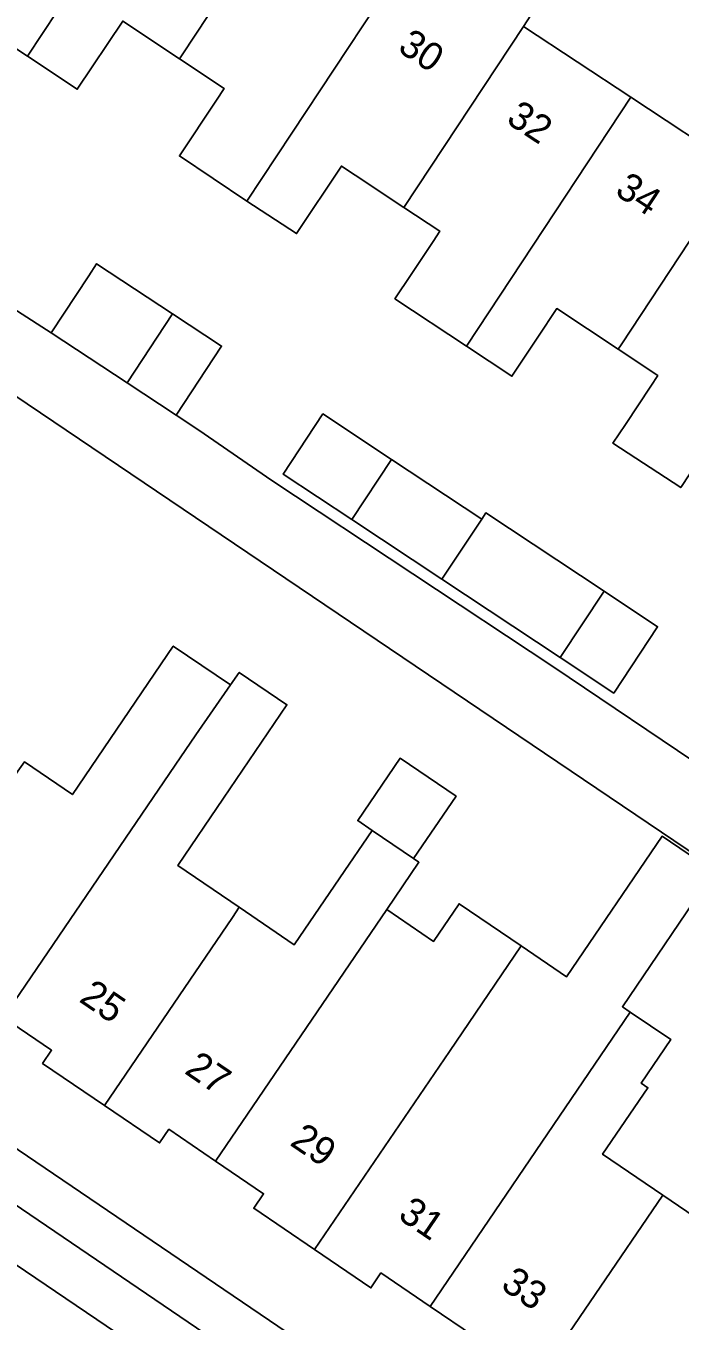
# Model space of a CAD drawing. Extents: x 159279 to 160377, y 384531 to 385888.
# Drawn here: x 159905.8 to 159929.07, y 384790.68 to 384836.73 of the extents above; entities that cross this region are included whole.
import ezdxf

# ---------------------------------------------------------------- set-up
doc = ezdxf.new("R2010")
doc.units = 0
for name, color, linetype in [('IMGEO_Erf', 7, 'Continuous'), ('IMGEO_Pand', 7, 'Continuous'), ('IMGEO_Pand_nummerreeks', 7, 'Continuous'), ('IMGEO_Parkeervlak_open', 7, 'Continuous'), ('IMGEO_Rijbaan_lokaal_open', 7, 'Continuous'), ('IMGEO_Voetpad_open', 7, 'Continuous')]:
    doc.layers.add(name, color=color, linetype=linetype)

msp = doc.modelspace()

# ---------------------------------------------------------------- linework, layer by layer
at = {"layer": 'IMGEO_Erf'}
for points in [[(159888.241, 384837.963), (159893.651, 384834.187), (159895.036, 384836.353), (159897.421, 384834.828), (159896.036, 384832.662), (159906.697, 384825.818), (159908.032, 384827.844), (159908.315, 384828.273), (159911.014, 384826.492), (159912.758, 384825.342), (159911.14, 384822.889), (159911.948, 384822.357), (159914.544, 384820.567), (159924.57, 384813.932), (159946.537, 384799.134)], [(159929.088, 384820.31), (159926.679, 384821.889), (159927.119, 384822.553), (159928.021, 384823.915), (159928.273, 384824.295), (159926.861, 384825.23), (159924.679, 384826.676), (159924.631, 384826.604), (159924.053, 384825.73), (159923.086, 384824.269), (159921.465, 384825.342), (159918.925, 384827.025), (159919.5, 384827.893), (159920.278, 384829.068), (159920.518, 384829.431), (159919.246, 384830.273), (159917.508, 384831.424), (159917.021, 384831.747), (159915.429, 384829.343), (159913.658, 384830.497), (159911.258, 384832.104), (159912.575, 384834.093), (159912.85, 384834.509), (159911.263, 384835.56), (159909.243, 384836.898), (159907.624, 384834.475), (159905.851, 384835.649), (159903.573, 384837.162)], [(159857.677, 384829.243), (159933.27, 384777.928)], [(159936.223, 384802.782), (159904.008, 384824.524)], [(159905.747, 384810.557), (159907.451, 384809.398), (159911.041, 384814.68), (159913.079, 384813.295), (159913.39, 384813.742), (159915.083, 384812.59), (159912.827, 384809.272), (159911.199, 384806.878), (159913.39, 384805.388), (159915.344, 384804.06), (159916.963, 384806.441), (159918.11, 384808.125), (159917.602, 384808.471), (159919.11, 384810.688), (159921.097, 384809.337), (159919.589, 384807.119), (159919.778, 384806.991), (159918.632, 384805.306), (159920.296, 384804.175), (159921.207, 384805.515), (159923.414, 384804.015), (159925.029, 384802.918), (159928.425, 384807.915), (159930.276, 384806.657), (159927.013, 384801.855), (159927.295, 384801.663), (159928.737, 384800.683), (159927.683, 384799.132), (159927.919, 384798.972), (159926.311, 384796.606), (159928.451, 384795.152), (159930.42, 384793.813)], [(159921.75, 384790.128), (159920.174, 384791.199), (159918.428, 384792.386), (159918.068, 384791.856), (159916.066, 384793.217), (159913.902, 384794.687), (159914.254, 384795.204), (159912.547, 384796.365), (159910.883, 384797.496), (159910.552, 384797.009), (159908.595, 384798.339), (159906.391, 384799.836), (159906.712, 384800.308), (159905.008, 384801.466)]]:
    msp.add_lwpolyline(points, dxfattribs=at)
msp.add_lwpolyline([(159922.011, 384819.189), (159922.157, 384819.41), (159926.36, 384816.626), (159928.267, 384815.362), (159926.706, 384813.005), (159924.795, 384814.271), (159920.595, 384817.052), (159917.387, 384819.177), (159914.945, 384820.795), (159916.36, 384822.932), (159918.799, 384821.316)], close=True, dxfattribs=at)
at = {"layer": 'IMGEO_Pand'}
for points in [[(159911.707, 384844.521), (159907.899, 384847.043), (159903.648, 384840.603), (159905.182, 384839.592), (159904.899, 384839.167), (159903.573, 384837.162), (159905.851, 384835.649), (159907.459, 384838.085)], [(159915.513, 384842.001), (159911.707, 384844.521), (159907.459, 384838.085), (159905.851, 384835.649), (159907.624, 384834.475), (159909.243, 384836.898), (159911.263, 384835.56), (159911.357, 384835.7)], [(159919.769, 384839.756), (159916.595, 384841.858), (159915.777, 384842.399), (159915.513, 384842.001), (159911.357, 384835.7), (159911.263, 384835.56), (159912.85, 384834.509), (159912.575, 384834.093), (159911.258, 384832.104), (159913.658, 384830.497), (159915.255, 384832.916)], [(159923.497, 384836.712), (159923.762, 384837.112), (159922.937, 384837.658), (159919.769, 384839.756), (159915.255, 384832.916), (159913.658, 384830.497), (159915.429, 384829.343), (159917.021, 384831.747), (159917.508, 384831.424), (159919.246, 384830.273)], [(159927.31, 384834.199), (159923.497, 384836.712), (159919.246, 384830.273), (159920.518, 384829.431), (159920.278, 384829.068), (159919.5, 384827.893), (159918.925, 384827.025), (159921.465, 384825.342), (159923.055, 384827.751)], [(159931.124, 384831.685), (159927.31, 384834.199), (159923.055, 384827.751), (159921.465, 384825.342), (159923.086, 384824.269), (159924.053, 384825.73), (159924.631, 384826.604), (159924.679, 384826.676), (159926.861, 384825.23), (159926.972, 384825.394)], [(159934.937, 384829.172), (159931.124, 384831.685), (159926.972, 384825.394), (159926.861, 384825.23), (159928.273, 384824.295), (159928.021, 384823.915), (159927.119, 384822.553), (159926.679, 384821.889), (159929.088, 384820.31), (159930.67, 384822.707)], [(159911.014, 384826.492), (159908.315, 384828.273), (159908.032, 384827.844), (159906.697, 384825.818), (159909.396, 384824.039)], [(159911.014, 384826.492), (159909.396, 384824.039), (159911.14, 384822.889), (159912.758, 384825.342)], [(159918.799, 384821.316), (159916.36, 384822.932), (159914.945, 384820.795), (159917.387, 384819.177)], [(159922.011, 384819.189), (159918.799, 384821.316), (159917.387, 384819.177), (159920.595, 384817.052)], [(159922.011, 384819.189), (159920.595, 384817.052), (159924.795, 384814.271), (159926.36, 384816.626), (159922.157, 384819.41)], [(159926.36, 384816.626), (159924.795, 384814.271), (159926.706, 384813.005), (159928.267, 384815.362)], [(159911.113, 384810.437), (159911.848, 384811.527), (159913.079, 384813.295), (159911.041, 384814.68), (159907.451, 384809.398), (159905.747, 384810.557), (159905.514, 384810.225), (159900.968, 384803.545), (159903.043, 384802.135), (159903.352, 384802.591), (159905.008, 384801.466)], [(159911.199, 384806.878), (159912.827, 384809.272), (159915.083, 384812.59), (159913.39, 384813.742), (159913.079, 384813.295), (159911.848, 384811.527), (159911.113, 384810.437), (159905.008, 384801.466), (159906.712, 384800.308), (159906.391, 384799.836), (159908.595, 384798.339), (159913.148, 384805.031), (159913.39, 384805.388)], [(159918.11, 384808.125), (159919.589, 384807.119), (159921.097, 384809.337), (159919.11, 384810.688), (159917.602, 384808.471)], [(159918.632, 384805.306), (159919.778, 384806.991), (159919.589, 384807.119), (159918.11, 384808.125), (159916.963, 384806.441), (159915.344, 384804.06), (159913.39, 384805.388), (159913.148, 384805.031), (159908.595, 384798.339), (159910.552, 384797.009), (159910.883, 384797.496), (159912.547, 384796.365)], [(159926.24, 384800.113), (159927.295, 384801.663), (159927.013, 384801.855), (159930.276, 384806.657), (159928.425, 384807.915), (159925.029, 384802.918), (159923.414, 384804.015), (159920.861, 384800.263), (159916.066, 384793.217), (159918.068, 384791.856), (159918.428, 384792.386), (159920.174, 384791.199)], [(159920.861, 384800.263), (159923.414, 384804.015), (159921.207, 384805.515), (159920.296, 384804.175), (159918.632, 384805.306), (159912.547, 384796.365), (159914.254, 384795.204), (159913.902, 384794.687), (159916.066, 384793.217)], [(159928.451, 384795.152), (159926.311, 384796.606), (159927.919, 384798.972), (159927.683, 384799.132), (159928.737, 384800.683), (159927.295, 384801.663), (159926.24, 384800.113), (159920.174, 384791.199), (159921.75, 384790.128), (159921.397, 384789.609), (159923.641, 384788.084)], [(159933.975, 384794.928), (159933.625, 384795.166), (159932.062, 384796.228), (159930.42, 384793.813), (159928.451, 384795.152), (159923.641, 384788.084), (159925.617, 384786.74), (159925.961, 384787.245), (159927.866, 384785.95)]]:
    msp.add_lwpolyline(points, close=True, dxfattribs=at)
at = {"layer": 'IMGEO_Parkeervlak_open'}
for points in [[(159841.061, 384836.342), (159869.05, 384817.352), (159885.17, 384806.406), (159887.611, 384804.749), (159908.324, 384790.738), (159926.959, 384778.09), (159945.396, 384765.37), (159945.552, 384765.562)], [(159918.388, 384786.002), (159885.211, 384808.551)]]:
    msp.add_lwpolyline(points, dxfattribs=at)
at = {"layer": 'IMGEO_Rijbaan_lokaal_open'}
for points in [[(159924.059, 384842.46), (159922.175, 384839.615), (159923.606, 384838.668), (159922.937, 384837.658), (159923.762, 384837.112), (159923.497, 384836.712), (159927.31, 384834.199), (159931.124, 384831.685), (159934.937, 384829.172), (159938.221, 384827.008), (159939.13, 384828.386), (159940.541, 384827.456), (159942.418, 384830.305)], [(159926.959, 384778.09), (159908.324, 384790.738), (159887.611, 384804.749), (159885.702, 384801.937), (159896.121, 384794.85), (159926.868, 384773.971), (159943.479, 384762.606), (159945.396, 384765.37)]]:
    msp.add_lwpolyline(points, close=True, dxfattribs=at)
at = {"layer": 'IMGEO_Voetpad_open'}
for points in [[(159946.537, 384799.134), (159924.57, 384813.932), (159914.544, 384820.567), (159911.948, 384822.357), (159911.14, 384822.889), (159909.396, 384824.039), (159906.697, 384825.818), (159896.036, 384832.662), (159893.651, 384834.187), (159888.241, 384837.963)], [(159885.292, 384837.269), (159886.778, 384836.259), (159886.708, 384836.156), (159904.008, 384824.524), (159936.223, 384802.782)], [(159945.552, 384765.562), (159947.447, 384768.384), (159942.761, 384771.531), (159933.683, 384777.648), (159933.27, 384777.928), (159857.677, 384829.243)], [(159885.211, 384808.551), (159918.388, 384786.002)]]:
    msp.add_lwpolyline(points, dxfattribs=at)

# ---------------------------------------------------------------- texts
at = {"layer": 'IMGEO_Pand_nummerreeks'}
for s, rotation, p in [('30', 326.5736, (159918.981, 384835.854)), ('32', 326.5736, (159922.839, 384833.307)), ('34', 326.5736, (159926.705, 384830.757)), ('25', 325.76, (159907.652, 384802.06)), ('27', 325.76, (159911.401, 384799.508)), ('29', 325.76, (159915.149, 384796.957)), ('31', 325.76, (159918.991, 384794.341)), ('33', 325.76, (159922.646, 384791.854))]:
    msp.add_text(s, height=1, rotation=rotation, dxfattribs=at).set_placement(p)

doc.saveas('drawing.dxf')
